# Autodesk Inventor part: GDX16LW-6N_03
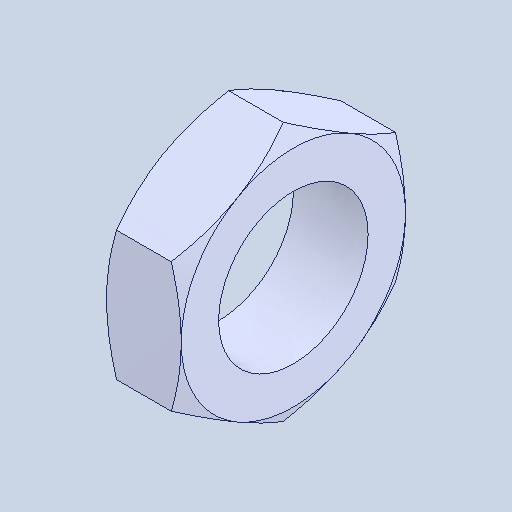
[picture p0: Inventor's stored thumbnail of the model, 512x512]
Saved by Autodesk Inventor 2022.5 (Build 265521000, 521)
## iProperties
Created: 2024-06
Part Number: GDX16LW-6N_03
Material: 一般
Document SubType Name: Modeling
Designer: ImaoCorp
Density: 1 g/cm^3
Appearance: 既定
Author: ImaoCorp
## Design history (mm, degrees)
feature "GDX16LW-6N_03"
node "ソリッド1"
